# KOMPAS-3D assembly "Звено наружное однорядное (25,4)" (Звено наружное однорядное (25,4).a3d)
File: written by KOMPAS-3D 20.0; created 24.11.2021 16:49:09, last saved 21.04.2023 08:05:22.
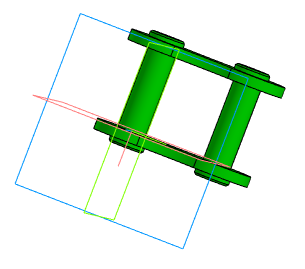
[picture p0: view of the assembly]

Document properties: Полное имя файла: C:\!WORK!\ЗИГ-18.240.00 Линия ЗигЗаг\Цепь\Звено наружное однорядное (25,4).a3d

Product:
- Part/product: Звено наружное однорядное (25,4)
    Масса: 0.0570492
  - Component [detail]: Заклепка цепи 8 (32.6)  | pos. 7  | Материал: Сталь 45  ГОСТ 1050-2013 (density 7810 kg/m3); Масса: 0.0134894; source file: Заклепка цепи 8 (32.6).m3d
  - Component [detail]: Заклепка цепи 8 (32.6)  | pos. 5  | Материал: Сталь 45  ГОСТ 1050-2013 (density 7810 kg/m3); Масса: 0.0134894; source file: Заклепка цепи 8 (32.6).m3d
  - Component [detail]: Пластина наружная (25,4)  | pos. 1  | Материал: Сталь 45  ГОСТ 1050-2013 (density 7810 kg/m3); Масса: 0.0150352; source file: Пластина наружная (25,4).m3d
  - Component [detail]: Пластина наружная (25,4)  | pos. 4  | Материал: Сталь 45  ГОСТ 1050-2013 (density 7810 kg/m3); Масса: 0.0150352; source file: Пластина наружная (25,4).m3d

Referenced files in C:\!WORK!\ЗИГ-18.240.00 Линия ЗигЗаг\Цепь\: Пластина наружная (25,4).m3d, Заклепка цепи 8 (32.6).m3d
Referenced files in C:\!WORK!\ЗИГ-18.240.00\Цепь\: Пластина наружная (25,4).m3d
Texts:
  SAPR-SVARKA-38 docBasicParam
  SAPR-SVARKA-38 docBodyParam
  SAPR-SVARKA-38 docWeldSignParam
  Пластина наружная (25,4) (1)
  Пластина наружная (25,4) (2)
  Заклепка цепи 8 (32.6) (1)
  Заклепка цепи 8 (32.6) (2)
